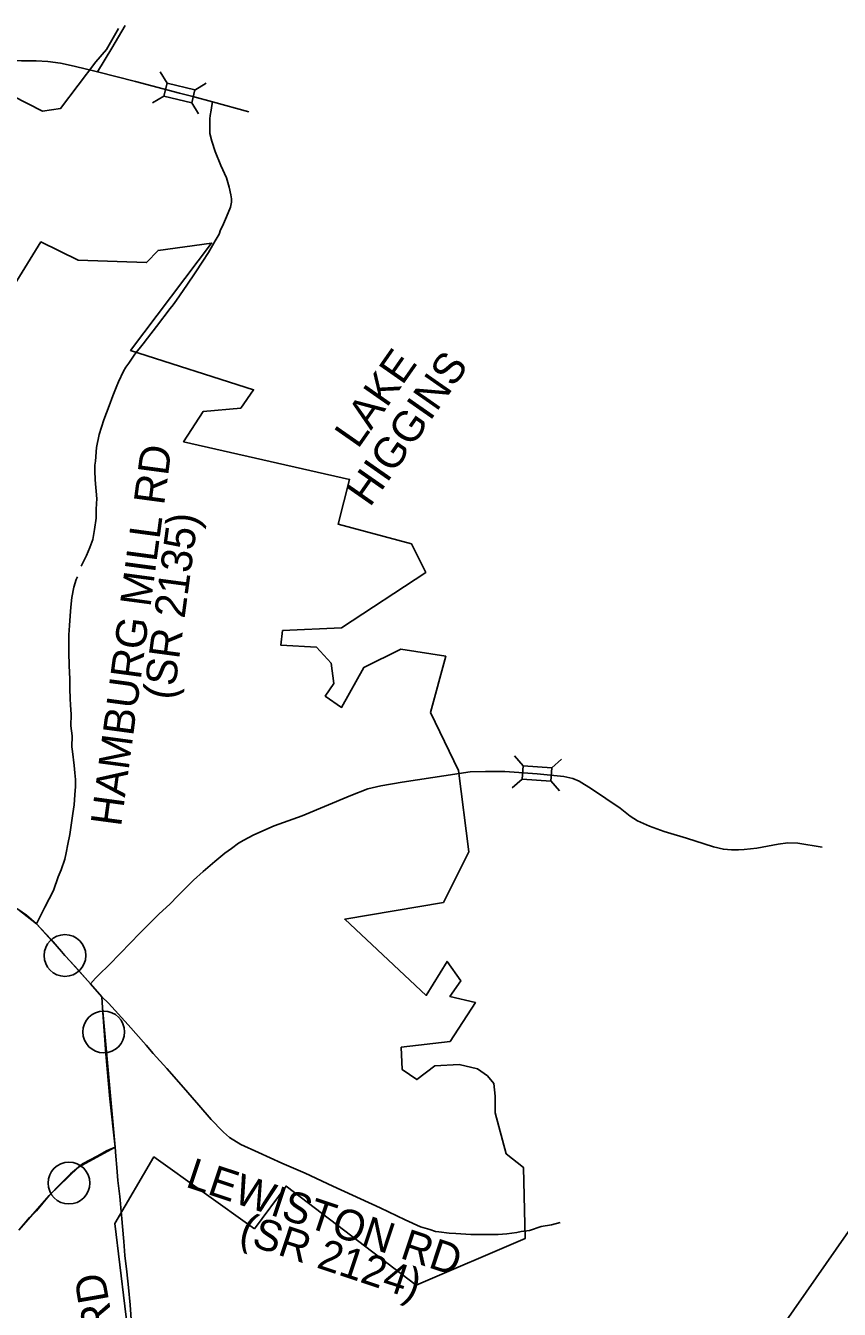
# Model space of a CAD drawing. Extents: x 1731327 to 1735374, y 884856 to 889832.
# Drawn here: x 1731582.7 to 1731719.5, y 885272.1 to 885487.8 of the extents above; entities that cross this region are included whole.
import ezdxf

# ---------------------------------------------------------------- set-up
doc = ezdxf.new("R2010")
doc.units = 0
for name, color, linetype in [('Exist Horizontal Baseline Alignment', 7, 'Continuous'), ('Exist Other Culture Located Object CELL', 7, 'Continuous'), ('Exist Other Culture Sign Text', 7, 'Continuous'), ('Exist Roads EOP Other Text', 7, 'Continuous'), ('Exist Structure Major Bridge Seat Top Elevation', 7, 'Continuous'), ('Exist Structure Major Deck Tunnel Box Culvert Text', 7, 'Continuous'), ('Exist Utilities Telephone UG Cable SUE', 7, 'Continuous')]:
    doc.layers.add(name, color=color, linetype=linetype)

msp = doc.modelspace()

# ---------------------------------------------------------------- linework, layer by layer
at = {"layer": 'Exist Horizontal Baseline Alignment'}
msp.add_line((1731631.46, 885157.08), (1731748.15, 885324.05), dxfattribs=at)
msp.add_lwpolyline([(1731581.43, 885339.32), (1731584.58, 885336.87), (1731593.65, 885326.8), (1731595.54, 885324.64), (1731595.68, 885322.77), (1731597.76, 885299.37), (1731591.61, 885296.03), (1731586.71, 885291.26), (1731581.61, 885285.42)], dxfattribs=at)
msp.add_lwpolyline([(1731581.43, 885339.32), (1731584.58, 885336.87), (1731593.65, 885326.8), (1731595.54, 885324.64), (1731595.68, 885322.77), (1731597.76, 885299.37), (1731591.61, 885296.03), (1731586.71, 885291.26), (1731581.61, 885285.42)], dxfattribs=at)
for centre in [(1731589.35, 885331.56), (1731595.86, 885318.72), (1731590.01, 885293.33)]:
    msp.add_circle(centre, 3.51, dxfattribs=at)
at = {"layer": 'Exist Other Culture Located Object CELL'}
msp.add_line((1731595.54, 885324.64), (1731593.65, 885326.8), dxfattribs=at)
for points in [[(1731594.82, 885480.03), (1731597.24, 885483.99), (1731599.44, 885487.76)], [(1731594.59, 885406.23), (1731594.59, 885406.5), (1731594.65, 885407.51), (1731594.68, 885408.3), (1731594.42, 885411.44), (1731594.34, 885412.99), (1731594.39, 885413.91), (1731594.48, 885414.62), (1731594.62, 885416.88), (1731595.11, 885419.08), (1731595.89, 885421.52), (1731596.77, 885423.91), (1731597.39, 885425.55), (1731598.05, 885427.23), (1731598.35, 885427.91), (1731599.21, 885429.7), (1731599.59, 885430.38), (1731600.07, 885431.08), (1731601.1, 885432.56), (1731602.49, 885434.31), (1731603.2, 885435.25), (1731604.75, 885437.25), (1731607.01, 885440.26), (1731607.51, 885440.89), (1731608.09, 885441.66), (1731609.84, 885444.19), (1731611.25, 885446.24), (1731612.5, 885448.21), (1731613.48, 885449.67), (1731614.56, 885451.59), (1731615.25, 885452.76), (1731615.51, 885453.45), (1731615.8, 885454.05), (1731616.5, 885455.65), (1731617.15, 885457.25), (1731617.33, 885458.11), (1731617.33, 885458.66), (1731617.22, 885459.33), (1731616.94, 885460.61), (1731616.5, 885462.17), (1731615.53, 885464.28), (1731614.58, 885466.6), (1731614.05, 885468.36), (1731613.71, 885469.62), (1731613.68, 885470.77), (1731613.68, 885472.12), (1731613.75, 885472.69), (1731613.89, 885473.59), (1731614, 885474.33), (1731614.14, 885474.99)], [(1731592.06, 885396.96), (1731592.99, 885398.78), (1731593.55, 885400.08), (1731594.02, 885401.43), (1731594.33, 885403.1), (1731594.59, 885405.05), (1731594.59, 885406.23)], [(1731590.6, 885365.81), (1731590.51, 885366.64), (1731590.55, 885368.49), (1731590.35, 885370.14), (1731590.39, 885372.05), (1731590.27, 885373.68), (1731590.21, 885374.7), (1731590.14, 885376.39), (1731590.14, 885378.04), (1731590.07, 885380.24), (1731590.06, 885380.79), (1731590.02, 885381.96), (1731590.02, 885383.91), (1731590.01, 885385.42), (1731590.13, 885386.98), (1731590.23, 885388.6), (1731590.35, 885390.1), (1731590.49, 885391.69), (1731590.81, 885393.43), (1731591.24, 885394.74), (1731591.43, 885395.2)], [(1731584.58, 885336.87), (1731585.97, 885339.67), (1731587.41, 885342.48), (1731588.21, 885344.8), (1731588.72, 885345.97), (1731589.33, 885347.74), (1731589.53, 885348.8), (1731589.83, 885350.27), (1731590.16, 885351.91), (1731590.69, 885355.43), (1731590.88, 885356.88), (1731591.03, 885358.55), (1731591.09, 885359.95), (1731591.1, 885361.1), (1731591.03, 885362.26), (1731590.92, 885363.5), (1731590.6, 885365.81)], [(1731668.68, 885362.1), (1731663.29, 885362.49), (1731660, 885362.48), (1731657.46, 885362.39), (1731651.15, 885361.48), (1731645.99, 885360.7)], [(1731677.84, 885359.54), (1731675.76, 885360.82), (1731674.72, 885361.3), (1731673.18, 885361.63), (1731668.68, 885362.1)], [(1731645.99, 885360.7), (1731642.44, 885360.07), (1731640.24, 885359.56), (1731637.41, 885358.42), (1731629.21, 885355.02), (1731624.53, 885353.32), (1731622.61, 885352.52), (1731620.99, 885351.75), (1731619.42, 885350.93), (1731618.53, 885350.44), (1731617.31, 885349.56), (1731616.22, 885348.75), (1731614.51, 885347.33), (1731612.59, 885345.68), (1731610.95, 885344.23), (1731608.32, 885341.6), (1731606.96, 885340.19), (1731605.16, 885338.54), (1731602.06, 885335.43), (1731600.18, 885333.52), (1731598.77, 885332.09), (1731596.6, 885329.84), (1731595.2, 885328.51), (1731594.5, 885327.76), (1731593.65, 885326.8)], [(1731716.57, 885349.77), (1731712.5, 885350.41), (1731710.8, 885350.5), (1731709.2, 885350.27), (1731705.6, 885349.57), (1731703.5, 885349.35), (1731702.56, 885349.33), (1731701.37, 885349.32), (1731700.01, 885349.42), (1731698.35, 885349.82), (1731696.76, 885350.34), (1731693.81, 885351.3), (1731690.59, 885352.25), (1731690.04, 885352.41), (1731687.59, 885353.27), (1731685.58, 885354.21), (1731684.34, 885354.96), (1731682.66, 885356.3), (1731677.84, 885359.54)], [(1731584.58, 885336.87), (1731582.91, 885338.32), (1731581.43, 885339.32), (1731579.58, 885340.37), (1731573.14, 885344.32)], [(1731588.77, 885332.23), (1731586.95, 885334.29), (1731584.58, 885336.87)], [(1731593.65, 885326.8), (1731590.98, 885329.79), (1731589.35, 885331.56), (1731588.77, 885332.23)], [(1731597.76, 885299.37), (1731596.88, 885307.49), (1731596.2, 885315.05), (1731595.68, 885322.77), (1731595.54, 885324.64)], [(1731660.02, 885284.72), (1731657.53, 885284.71), (1731655.02, 885284.84), (1731653.9, 885284.9), (1731652.2, 885285.14), (1731651.6, 885285.19), (1731650.65, 885285.51), (1731649.1, 885286.01), (1731646.52, 885287.17), (1731642.31, 885289.18), (1731634.37, 885292.83), (1731629.72, 885294.98), (1731625.78, 885296.68), (1731621.85, 885298.49), (1731618.91, 885299.84), (1731617.01, 885300.98), (1731615.98, 885301.9), (1731615.12, 885302.71), (1731614.57, 885303.32), (1731613.92, 885304.02), (1731611.85, 885306.41), (1731608.88, 885309.82), (1731606.44, 885312.57), (1731604.17, 885315.09), (1731602.98, 885316.5), (1731599.96, 885319.94), (1731596.69, 885323.55), (1731595.54, 885324.64)], [(1731581.61, 885285.42), (1731583.39, 885287.53), (1731584.55, 885288.67), (1731586.71, 885291.26), (1731588.53, 885293.14), (1731590.27, 885294.89), (1731591.61, 885296.03), (1731592.31, 885296.57), (1731593.6, 885297.22), (1731594.74, 885297.84), (1731596.33, 885298.73), (1731597.76, 885299.37)], [(1731600.54, 885269.66), (1731600.3, 885272.86), (1731600, 885275.82), (1731599.72, 885278.42), (1731599.43, 885281.19), (1731599.23, 885283.51), (1731598.84, 885287.94), (1731598.57, 885291.07), (1731598.25, 885293.76), (1731598.07, 885295.96), (1731597.89, 885297.83), (1731597.76, 885299.37)], [(1731672.57, 885286.72), (1731671.11, 885286.31), (1731669.39, 885286.02), (1731667.4, 885285.39), (1731666.02, 885285.19), (1731665.3, 885285.04), (1731663.59, 885284.8), (1731662.13, 885284.68), (1731660.02, 885284.72)]]:
    msp.add_lwpolyline(points, dxfattribs=at)
at = {"layer": 'Exist Other Culture Sign Text'}
for points in [[(1731598.36, 885487.3), (1731596.31, 885483.75), (1731594.56, 885481.67), (1731588.62, 885473.85), (1731585.56, 885473.42), (1731577.93, 885477.27)], [(1731574.63, 885434.26), (1731585.3, 885451.43), (1731591.56, 885448.38), (1731603.05, 885447.96), (1731605, 885450), (1731613.99, 885451.24), (1731600.37, 885433.21), (1731621.04, 885426.6), (1731618.88, 885423.51)], [(1731618.88, 885423.51), (1731612.59, 885422.96), (1731609.27, 885417.85), (1731637.18, 885411.54), (1731635.28, 885404.01), (1731647.57, 885400.7), (1731649.98, 885395.91), (1731635.84, 885386.63), (1731625.92, 885386.13), (1731625.64, 885383.69), (1731631.63, 885383.34), (1731634.08, 885380.67), (1731634.55, 885377.23), (1731633.09, 885375.14), (1731635.82, 885373.23), (1731639.56, 885379.96), (1731645.78, 885383.04), (1731653.33, 885381.84), (1731650.78, 885372.37), (1731655.48, 885362.63), (1731657.2, 885348.97), (1731652.94, 885340.46), (1731636.37, 885337.65), (1731650.07, 885324.86), (1731653.57, 885330.56), (1731655.87, 885327.31), (1731654.04, 885324.68), (1731658.33, 885323.64), (1731654.07, 885317.13), (1731645.86, 885316.16), (1731646.03, 885312.41), (1731648.47, 885310.71), (1731651.5, 885313.05), (1731655.57, 885313.28), (1731658.67, 885312.52), (1731660.36, 885311.34), (1731661.41, 885310.05), (1731661.62, 885307.95), (1731661.62, 885305.16), (1731663.51, 885298.26), (1731666.38, 885295.97), (1731666.7, 885284.03), (1731648.37, 885276.17), (1731626.5, 885292.82), (1731621.21, 885285.63)], [(1731621.21, 885285.63), (1731604.29, 885297.72), (1731597.71, 885286.54), (1731601.08, 885258.79), (1731602.72, 885243.98), (1731603.2, 885239.96), (1731604.85, 885234.71), (1731606.54, 885230.67), (1731608.72, 885220.89), (1731623.22, 885216.66)]]:
    msp.add_lwpolyline(points, dxfattribs=at)
at = {"layer": 'Exist Roads EOP Other Text'}
for points in [[(1731594.82, 885480.03), (1731590.92, 885480.95), (1731588.57, 885481.48), (1731586.45, 885481.75), (1731584.48, 885481.83), (1731582.05, 885481.85), (1731577.86, 885481.9), (1731573.36, 885482), (1731566.72, 885482.1), (1731560.93, 885482.18), (1731556.89, 885482.2), (1731551.82, 885482.3), (1731545.82, 885482.38), (1731543.29, 885482.41), (1731538.5, 885482.62), (1731536.16, 885482.93), (1731531.83, 885483.76)], [(1731608.57, 885476.44), (1731601.19, 885478.39), (1731594.82, 885480.03)], [(1731614.14, 885474.99), (1731610.82, 885475.84), (1731608.57, 885476.44)], [(1731620.22, 885473.26), (1731614.14, 885474.99)]]:
    msp.add_lwpolyline(points, dxfattribs=at)
at = {"layer": 'Exist Structure Major Bridge Seat Top Elevation'}
for p, q in [((1731605.36, 885480), (1731606.5, 885478.11)), ((1731611.18, 885476.95), (1731613.07, 885478.09)), ((1731604.07, 885474.78), (1731605.95, 885475.92)), ((1731610.65, 885474.81), (1731611.79, 885472.92))]:
    msp.add_line(p, q, dxfattribs=at)
msp.add_lwpolyline([(1731606.5, 885478.11), (1731611.18, 885476.96), (1731610.64, 885474.77), (1731605.95, 885475.92)], close=True, dxfattribs=at)
at = {"layer": 'Exist Utilities Telephone UG Cable SUE'}
for p, q in [((1731664.88, 885365.09), (1731666.32, 885363.42)), ((1731671.14, 885363.08), (1731672.81, 885364.53)), ((1731664.5, 885359.73), (1731666.17, 885361.17)), ((1731670.99, 885360.88), (1731672.44, 885359.21))]:
    msp.add_line(p, q, dxfattribs=at)
msp.add_lwpolyline([(1731666.32, 885363.42), (1731671.14, 885363.09), (1731670.99, 885360.84), (1731666.17, 885361.17)], close=True, dxfattribs=at)

# ---------------------------------------------------------------- texts
at = {"layer": 'Exist Structure Major Deck Tunnel Box Culvert Text'}
for s, rotation, p in [('LAKE ', 55.0911, (1731638.57, 885416.53)), ('HIGGINS', 55.0911, (1731640.59, 885406.73)), ('HAMBURG MILL RD', 82.3683, (1731598.76, 885353.1)), ('(SR 2135)', 82.3683, (1731607.6, 885374.38)), ('LEWISTON RD', 341.6455, (1731609.43, 885292.76)), ('(SR 2124)', 341.6455, (1731618.34, 885283.54)), ('PLEASANT RIDGE RD', 99.912, (1731608.25, 885207.85))]:
    msp.add_text(s, height=5.163, rotation=rotation, dxfattribs=at).set_placement(p)

doc.saveas('drawing.dxf')
